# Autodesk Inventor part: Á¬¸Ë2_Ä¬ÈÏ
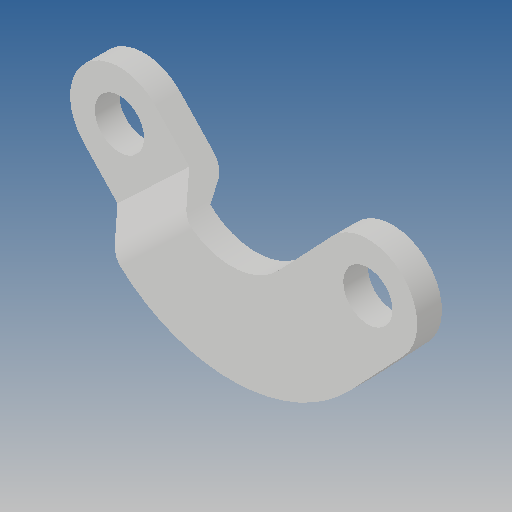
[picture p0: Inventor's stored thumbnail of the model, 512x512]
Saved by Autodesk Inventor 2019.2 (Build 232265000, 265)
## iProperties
Created: 2012-09
Part Number: Á¬¸Ë2_Ä¬ÈÏ
Material: Ogólny
Document SubType Name: Modeling
Designer: CADENGINEERING4
Density: 1 g/cm^3
Appearance: Domyślna
Author: CADENGINEERING4
Revision Number: ÈÎºÎ
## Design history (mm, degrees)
feature "NONE"
node "Bryła1"
